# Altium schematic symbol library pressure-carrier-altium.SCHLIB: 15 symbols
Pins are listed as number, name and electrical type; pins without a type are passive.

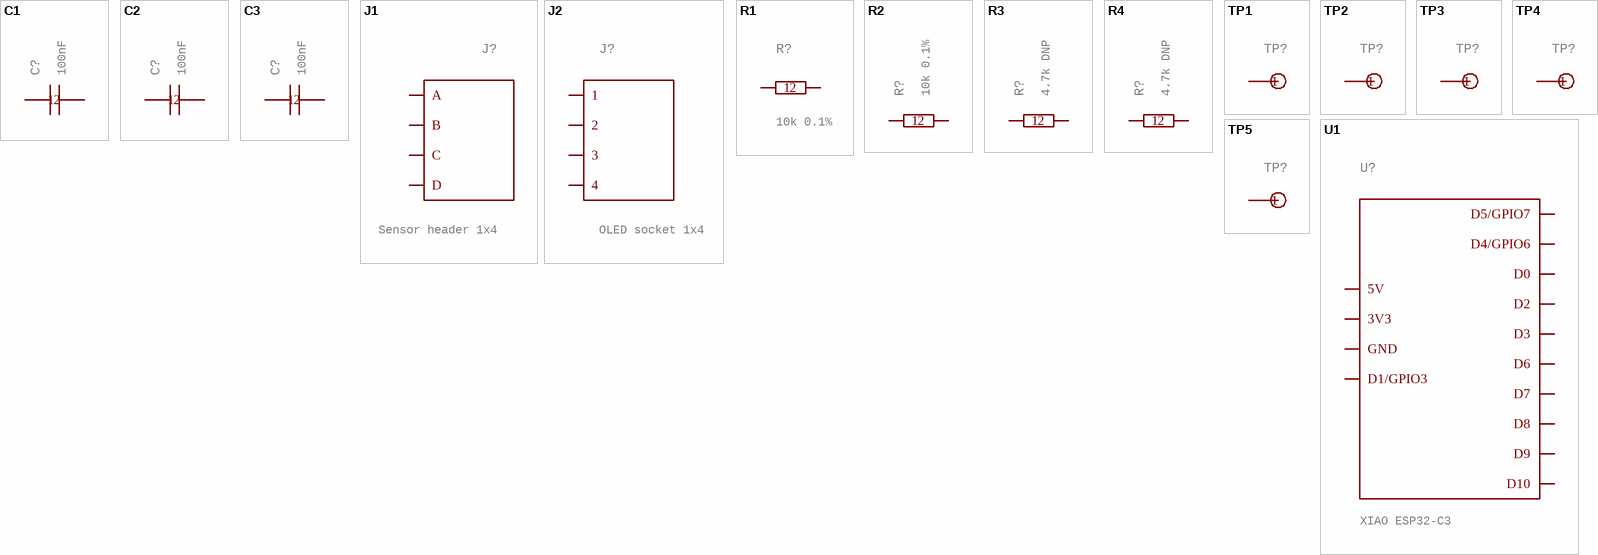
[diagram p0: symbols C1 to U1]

## C1
designator C?, comment 100nF
Manufacturer: TDK; Manufacturer Part Number: C1608X7R1H104K080AA; Part Kind: Manufacturer part; GateName_1: G$1; SymbolName_1: C1; ASSEMBLY: Fit; 100nF, 10%, X7R, 50V, 0603; 0.8mm square reflow lands.; Populate: Yes
footprint TDK_C1608_0603
pins: 1, 2

## C2
designator C?, comment 100nF
Manufacturer: TDK; Manufacturer Part Number: C1608X7R1H104K080AA; Part Kind: Manufacturer part; GateName_1: G$1; SymbolName_1: C2; ASSEMBLY: Fit; 100nF, 10%, X7R, 50V, 0603; 0.8mm square reflow lands.; Populate: Yes
footprint TDK_C1608_0603
pins: 1, 2

## C3
designator C?, comment 100nF
Manufacturer: TDK; Manufacturer Part Number: C1608X7R1H104K080AA; Part Kind: Manufacturer part; GateName_1: G$1; SymbolName_1: C3; ASSEMBLY: Fit; 100nF, 10%, X7R, 50V, 0603; 0.8mm square reflow lands.; Populate: Yes
footprint TDK_C1608_0603
pins: 1, 2

## J1
designator J?, comment Sensor header 1x4
Manufacturer: Samtec; Manufacturer Part Number: TSW-104-07-T-S; Part Kind: Manufacturer part; GateName_1: G$1; SymbolName_1: J1; ASSEMBLY: 2.54mm male adapter header; external sensor cable mating not established.; Populate: Yes; External Device Reference: MGPR guide chapter 4 transducer; individual MPN not stated
footprint Samtec_TSW104_THT
pins: 1 A, 2 B, 3 C, 4 D

## J2
designator J?, comment OLED socket 1x4
Manufacturer: Samtec; Manufacturer Part Number: SSQ-104-03-G-S-LL; Part Kind: Manufacturer part; GateName_1: G$1; SymbolName_1: J2; ASSEMBLY: 2.54mm female socket with locking leads; confirm external OLED pin order.; Populate: Yes; External Device Reference: ANAVI 0.96-inch SSD1306 I2C OLED; GND VCC SCL SDA
footprint Samtec_SSQ104_LL_THT
pins: 1, 2, 3, 4

## R1
designator R?, comment 10k 0.1%
Manufacturer: YAGEO; Manufacturer Part Number: RT0603BRD0710KL; Part Kind: Manufacturer part; GateName_1: G$1; SymbolName_1: R1; ASSEMBLY: Fit; 10k, 0.1%, 0.1W thin-film, 0603.; Populate: Yes
footprint YAGEO_RT0603_1608
pins: 1, 2

## R2
designator R?, comment 10k 0.1%
Manufacturer: YAGEO; Manufacturer Part Number: RT0603BRD0710KL; Part Kind: Manufacturer part; GateName_1: G$1; SymbolName_1: R2; ASSEMBLY: Fit; 10k, 0.1%, 0.1W thin-film, 0603.; Populate: Yes
footprint YAGEO_RT0603_1608
pins: 1, 2

## R3
designator R?, comment 4.7k DNP
Manufacturer: YAGEO; Manufacturer Part Number: AC0603FR-074K7L; Part Kind: Manufacturer part; GateName_1: G$1; SymbolName_1: R3; ASSEMBLY: DNP if OLED already has suitable pull-ups; 4.7k, 1%, 0.1W, 0603.; Populate: No
footprint YAGEO_AC0603_1608
pins: 1, 2

## R4
designator R?, comment 4.7k DNP
Manufacturer: YAGEO; Manufacturer Part Number: AC0603FR-074K7L; Part Kind: Manufacturer part; GateName_1: G$1; SymbolName_1: R4; ASSEMBLY: DNP if OLED already has suitable pull-ups; 4.7k, 1%, 0.1W, 0603.; Populate: No
footprint YAGEO_AC0603_1608
pins: 1, 2

## TP1
designator TP?, comment Bare PCB test pad  (value not drawn)
Part Kind: PCB feature; GateName_1: G$1; SymbolName_1: TP1; ASSEMBLY: Bare plated PCB feature; no purchased component. 1.2mm hole, 1.8mm copper.; Populate: No
footprint PCB_TestPad_PTH_1p2_D1p8
pins: 1

## TP2
designator TP?, comment Bare PCB test pad  (value not drawn)
Part Kind: PCB feature; GateName_1: G$1; SymbolName_1: TP2; ASSEMBLY: Bare plated PCB feature; no purchased component. 1.2mm hole, 1.8mm copper.; Populate: No
footprint PCB_TestPad_PTH_1p2_D1p8
pins: 1

## TP3
designator TP?, comment Bare PCB test pad  (value not drawn)
Part Kind: PCB feature; GateName_1: G$1; SymbolName_1: TP3; ASSEMBLY: Bare plated PCB feature; no purchased component. 1.2mm hole, 1.8mm copper.; Populate: No
footprint PCB_TestPad_PTH_1p2_D1p8
pins: 1

## TP4
designator TP?, comment Bare PCB test pad  (value not drawn)
Part Kind: PCB feature; GateName_1: G$1; SymbolName_1: TP4; ASSEMBLY: Bare plated PCB feature; no purchased component. 1.2mm hole, 1.8mm copper.; Populate: No
footprint PCB_TestPad_PTH_1p2_D1p8
pins: 1

## TP5
designator TP?, comment Bare PCB test pad  (value not drawn)
Part Kind: PCB feature; GateName_1: G$1; SymbolName_1: TP5; ASSEMBLY: Bare plated PCB feature; no purchased component. 1.2mm hole, 1.8mm copper.; Populate: No
footprint PCB_TestPad_PTH_1p2_D1p8
pins: 1

## U1
designator U?, comment XIAO ESP32-C3
Manufacturer: Seeed Studio; Manufacturer Part Number: 113991054; Part Kind: Manufacturer part; Socket MPN: SSQ-107-03-G-S-LL; GateName_1: G$1; SymbolName_1: U1; ASSEMBLY: Removable XIAO on two Samtec SSQ-107-03-G-S-LL female sockets; 1.02mm holes.; Populate: Yes; Socket Quantity: 2
footprint Seeed_XIAO_ESP32C3_THT
pins: 1 D0, 2 D1/GPIO3, 3 D2, 4 D3, 5 D4/GPIO6, 6 D5/GPIO7, 7 D6, 8 D7, 9 D8, 10 D9, 11 D10, 12 3V3, 13 GND, 14 5V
